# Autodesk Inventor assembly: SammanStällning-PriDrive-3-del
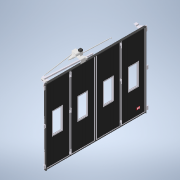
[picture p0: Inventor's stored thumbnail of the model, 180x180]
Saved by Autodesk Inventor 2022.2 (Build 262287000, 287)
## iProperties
Created: 2022-02
Part Number: SammanStällning-PriDrive-3-del
Document SubType Name: Assembly
Designer: cl
Author: cl
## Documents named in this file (22)
- G:\AutoCad\Carl Lund\3D-modeller systemlösningar\3D-modell-systemlösning-2022\SammanStällning-PriDrive-3-del.iam
- G:\AutoCad\Carl Lund\3D-modeller systemlösningar\3D-modell-systemlösning-2022\Parts\BladKomplett2022.iam
- G:\AutoCad\Carl Lund\3D-modeller systemlösningar\3D-modell-systemlösning-2022\Parts\MellanGångjärnH.ipt
- G:\AutoCad\Carl Lund\3D-modeller systemlösningar\3D-modell-systemlösning-2022\Parts\MellanGångjärnV.ipt
- G:\AutoCad\Carl Lund\3D-modeller systemlösningar\3D-modell-systemlösning-2022\Parts\Karmstyrning.ipt
- G:\AutoCad\Carl Lund\3D-modeller systemlösningar\3D-modell-systemlösning-2022\Parts\SidotätningUppe.ipt
- G:\AutoCad\Carl Lund\3D-modeller systemlösningar\3D-modell-systemlösning-2022\Parts\SidoTätning.ipt
- G:\AutoCad\Carl Lund\3D-modeller systemlösningar\3D-modell-systemlösning-2022\Parts\SläpList.ipt
- G:\AutoCad\Carl Lund\3D-modeller systemlösningar\3D-modell-systemlösning-2022\Parts\GummilistMellan.ipt
- G:\AutoCad\Carl Lund\3D-modeller systemlösningar\3D-modell-systemlösning-2022\Styrande.iam
- G:\AutoCad\Carl Lund\3D-modeller systemlösningar\3D-modell-systemlösning-2022\Parts\PriDrive\Karmgångjärn-PriDrive.ipt
- G:\AutoCad\Carl Lund\3D-modeller systemlösningar\3D-modell-systemlösning-2022\Parts\PriDrive\VinkeljärnStyrskena2.ipt
- G:\AutoCad\Carl Lund\3D-modeller systemlösningar\3D-modell-systemlösning-2022\Parts\PriDrive\VinkeljärnStyrskena.ipt
- G:\AutoCad\Carl Lund\3D-modeller systemlösningar\3D-modell-systemlösning-2022\Parts\StyrrulleH.ipt
- G:\AutoCad\Carl Lund\3D-modeller systemlösningar\3D-modell-systemlösning-2022\Parts\MotorKåpa.ipt
- G:\AutoCad\Carl Lund\3D-modeller systemlösningar\3D-modell-systemlösning-2022\Parts\Motor.ipt
- G:\AutoCad\Carl Lund\3D-modeller systemlösningar\3D-modell-systemlösning-2022\Parts\Växellåda.ipt
- G:\AutoCad\Carl Lund\3D-modeller systemlösningar\3D-modell-systemlösning-2022\Parts\MotorPlatta-3del.ipt
- G:\AutoCad\Carl Lund\3D-modeller systemlösningar\3D-modell-systemlösning-2022\Parts\Länkarm2-3Del.ipt
- G:\AutoCad\Carl Lund\3D-modeller systemlösningar\3D-modell-systemlösning-2022\Parts\Länkarm-3Del.ipt
- G:\AutoCad\Carl Lund\3D-modeller systemlösningar\3D-modell-systemlösning-2022\Parts\Styrskena-PD.ipt
- G:\AutoCad\Carl Lund\3D-modeller systemlösningar\3D-modell-systemlösning-2022\Parts\Logga.ipt
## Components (43 placed, 20 different names)
1. Logga:1 — Mate:200, Mate:201, Mate:202
2. BladKomplett2022:1 [sub-assembly] — Mate:1, Mate:2, Flush:1, Flush:2, Flush:3, Flush:8, Flush:28, Flush:29, Mate:28, Flush:30, Mate:42, Mate:39, Mate:43, Flush:99, Flush:100, Flush:101, Flush:102, Flush:103, Flush:104, Flush:112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
3. BladKomplett2022:2 [sub-assembly] — Flush:2, Flush:3, Flush:8, Flush:106, Mate:52, Flush:107, Flush:118, Flush:121, Mate:65, Flush:148, Flush:149, Mate:185, Flush:182, Flush:183, Flush:197
4. BladKomplett2022:3 [sub-assembly] — Flush:30, Flush:101, Flush:102, Mate:53, Flush:114, Flush:115, Flush:180, Mate:198
5. BladKomplett2022:4 [sub-assembly] — Flush:32, Flush:100, Flush:103, Mate:54, Flush:122, Flush:123, Flush:128, Mate:64, Flush:146, Flush:147
6. BladKomplett2022:5 [sub-assembly] — Flush:31, Flush:99, Flush:104, Flush:129, Mate:55, Flush:130, Mate:63, Flush:144, Flush:145, Flush:189
7. BladKomplett2022:6 [sub-assembly] — Mate:28, Flush:28, Flush:29, Flush:31, Flush:32, Mate:38, Flush:131, Flush:134, Flush:137, Mate:56, Flush:138, Flush:139, Mate:58, Mate:59, Mate:62, Flush:142, Flush:143, Flush:152, Mate:69, Mate:70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
8. Karmstyrning:2 — Mate:38, Mate:56, Flush:138, Flush:141
9. Karmstyrning:3 — Mate:39, Mate:43, Flush:140
10. Karmstyrning:4 — Mate:42, Mate:60, Mate:61, Flush:141
11. Karmstyrning:1 — Flush:139, Mate:58, Mate:59, Flush:140
12. MellanGångjärnV:3 — Flush:110, Flush:111, Flush:113
13. MellanGångjärnV:2 — Flush:108, Flush:109, Flush:110, Flush:111, Flush:112
14. MellanGångjärnV:1 — Flush:106, Mate:52, Flush:107, Flush:108, Flush:109
15. MellanGångjärnH:2 — Flush:116, Flush:117, Flush:118, Flush:119, Flush:120
16. MellanGångjärnH:3 — Flush:119, Flush:120, Flush:121
17. MellanGångjärnH:1 — Mate:53, Flush:114, Flush:115, Flush:116, Flush:117
18. MellanGångjärnV:6 — Flush:124, Flush:125, Flush:126, Flush:127, Flush:128
19. MellanGångjärnV:5 — Flush:126, Flush:127, Flush:129
20. MellanGångjärnV:4 — Mate:54, Flush:122, Flush:123, Flush:124, Flush:125
21. MellanGångjärnH:5 — Flush:132, Flush:133, Flush:134
22. MellanGångjärnH:6 — Flush:135, Flush:136, Flush:137
23. MellanGångjärnH:4 — Mate:55, Flush:130, Flush:131, Flush:132, Flush:133, Flush:135, Flush:136
24. GummilistMellan:2 — Mate:63, Flush:144, Flush:145
25. GummilistMellan:3 — Mate:64, Flush:146, Flush:147
26. GummilistMellan:4 — Mate:65, Flush:148, Flush:149
27. GummilistMellan:5 — Mate:66, Flush:150, Flush:151
28. SidotätningUppe:1 — Mate:67, Mate:68, Flush:152, Mate:71, Mate:74
29. SidoTätning:1 — Mate:69, Mate:70, Mate:71, Mate:76
30. SidoTätning:2 — Mate:72, Mate:73, Mate:74
31. SläpList:1 — Mate:75, Flush:153, Mate:76
32. GummilistMellan:1 — Mate:62, Flush:142, Flush:143
33. Karmgångjärn-PriDrive:1 — Mate:177, Flush:176, Mate:178, Flush:179, Mate:188, Tangent:3, Tangent:4
34. VinkeljärnStyrskena2:1 — Flush:179, Flush:180, Mate:181, Mate:183, Flush:187
35. VinkeljärnStyrskena:2 — Mate:187, Flush:187, Mate:199
36. StyrrulleH:1 — Mate:185, Flush:182, Flush:183, Tangent:2
37. Styrskena-PD:1 — Mate:181, Mate:183, Tangent:2, Mate:187, Mate:198
38. Länkarm-3Del:1 — Flush:190, Tangent:3, Flush:191, Mate:197
39. Länkarm2-3Del:1 — Flush:191, Mate:196, Tangent:4
40. MotorKåpa:1 — Mate:195, Flush:195, Flush:196
41. Motor:1 — Mate:193, Flush:194, Mate:194, Mate:195, Flush:195, Flush:196
42. Växellåda:1 — Mate:192, Flush:192, Flush:193, Flush:194, Mate:194
43. MotorPlatta-3del:1 — Mate:188, Flush:189, Flush:190, Mate:192, Flush:192, Flush:193, Mate:193, Flush:197, Mate:196, Mate:197, Mate:199
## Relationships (130: Flush 78, Mate 49, Tangent 3)
- Mate:1: BladKomplett2022:1
- Mate:2: BladKomplett2022:1
- Flush:1: BladKomplett2022:1
- Flush:2: BladKomplett2022:1 ↔ BladKomplett2022:2
- Flush:3: BladKomplett2022:1 ↔ BladKomplett2022:2
- Flush:8: BladKomplett2022:1 ↔ BladKomplett2022:2
- Mate:28: BladKomplett2022:1 ↔ BladKomplett2022:6
- Flush:28: BladKomplett2022:1 ↔ BladKomplett2022:6
- Flush:29: BladKomplett2022:1 ↔ BladKomplett2022:6
- Flush:30: BladKomplett2022:1 ↔ BladKomplett2022:3
- Flush:31: BladKomplett2022:5 ↔ BladKomplett2022:6
- Flush:32: BladKomplett2022:4 ↔ BladKomplett2022:6
- Mate:38: BladKomplett2022:6 ↔ Karmstyrning:2
- Mate:39: BladKomplett2022:1 ↔ Karmstyrning:3
- Mate:42: BladKomplett2022:1 ↔ Karmstyrning:4
- Mate:43: BladKomplett2022:1 ↔ Karmstyrning:3
- Flush:99: BladKomplett2022:1 ↔ BladKomplett2022:5
- Flush:100: BladKomplett2022:1 ↔ BladKomplett2022:4
- Flush:101: BladKomplett2022:1 ↔ BladKomplett2022:3
- Flush:102: BladKomplett2022:1 ↔ BladKomplett2022:3
- Flush:103: BladKomplett2022:1 ↔ BladKomplett2022:4
- Flush:104: BladKomplett2022:1 ↔ BladKomplett2022:5
- Flush:106: BladKomplett2022:2 ↔ MellanGångjärnV:1
- Mate:52: BladKomplett2022:2 ↔ MellanGångjärnV:1
- Flush:107: BladKomplett2022:2 ↔ MellanGångjärnV:1
- Flush:108: MellanGångjärnV:2 ↔ MellanGångjärnV:1
- Flush:109: MellanGångjärnV:2 ↔ MellanGångjärnV:1
- Flush:110: MellanGångjärnV:3 ↔ MellanGångjärnV:2
- Flush:111: MellanGångjärnV:3 ↔ MellanGångjärnV:2
- Flush:112: BladKomplett2022:1 ↔ MellanGångjärnV:2
- Flush:113: BladKomplett2022:1 ↔ MellanGångjärnV:3
- Mate:53: BladKomplett2022:3 ↔ MellanGångjärnH:1
- Flush:114: BladKomplett2022:3 ↔ MellanGångjärnH:1
- Flush:115: BladKomplett2022:3 ↔ MellanGångjärnH:1
- Flush:116: MellanGångjärnH:2 ↔ MellanGångjärnH:1
- Flush:117: MellanGångjärnH:2 ↔ MellanGångjärnH:1
- Flush:118: BladKomplett2022:2 ↔ MellanGångjärnH:2
- Flush:119: MellanGångjärnH:2 ↔ MellanGångjärnH:3
- Flush:120: MellanGångjärnH:2 ↔ MellanGångjärnH:3
- Flush:121: BladKomplett2022:2 ↔ MellanGångjärnH:3
- Mate:54: BladKomplett2022:4 ↔ MellanGångjärnV:4
- Flush:122: BladKomplett2022:4 ↔ MellanGångjärnV:4
- Flush:123: BladKomplett2022:4 ↔ MellanGångjärnV:4
- Flush:124: MellanGångjärnV:6 ↔ MellanGångjärnV:4
- Flush:125: MellanGångjärnV:6 ↔ MellanGångjärnV:4
- Flush:126: MellanGångjärnV:6 ↔ MellanGångjärnV:5
- Flush:127: MellanGångjärnV:6 ↔ MellanGångjärnV:5
- Flush:128: BladKomplett2022:4 ↔ MellanGångjärnV:6
- Flush:129: BladKomplett2022:5 ↔ MellanGångjärnV:5
- Mate:55: BladKomplett2022:5 ↔ MellanGångjärnH:4
- Flush:130: BladKomplett2022:5 ↔ MellanGångjärnH:4
- Flush:131: BladKomplett2022:6 ↔ MellanGångjärnH:4
- Flush:132: MellanGångjärnH:5 ↔ MellanGångjärnH:4
- Flush:133: MellanGångjärnH:5 ↔ MellanGångjärnH:4
- Flush:134: BladKomplett2022:6 ↔ MellanGångjärnH:5
- Flush:135: MellanGångjärnH:6 ↔ MellanGångjärnH:4
- Flush:136: MellanGångjärnH:6 ↔ MellanGångjärnH:4
- Flush:137: BladKomplett2022:6 ↔ MellanGångjärnH:6
- Mate:56: BladKomplett2022:6 ↔ Karmstyrning:2
- Flush:138: BladKomplett2022:6 ↔ Karmstyrning:2
- Flush:139: BladKomplett2022:6 ↔ Karmstyrning:1
- Mate:58: BladKomplett2022:6 ↔ Karmstyrning:1
- Mate:59: BladKomplett2022:6 ↔ Karmstyrning:1
- Flush:140: Karmstyrning:3 ↔ Karmstyrning:1
- Mate:60: BladKomplett2022:1 ↔ Karmstyrning:4
- Mate:61: BladKomplett2022:1 ↔ Karmstyrning:4
- Flush:141: Karmstyrning:2 ↔ Karmstyrning:4
- Mate:62: BladKomplett2022:6 ↔ GummilistMellan:1
- Flush:142: BladKomplett2022:6 ↔ GummilistMellan:1
- Flush:143: BladKomplett2022:6 ↔ GummilistMellan:1
- Mate:63: BladKomplett2022:5 ↔ GummilistMellan:2
- Flush:144: BladKomplett2022:5 ↔ GummilistMellan:2
- Flush:145: BladKomplett2022:5 ↔ GummilistMellan:2
- Mate:64: BladKomplett2022:4 ↔ GummilistMellan:3
- Flush:146: BladKomplett2022:4 ↔ GummilistMellan:3
- Flush:147: BladKomplett2022:4 ↔ GummilistMellan:3
- Mate:65: BladKomplett2022:2 ↔ GummilistMellan:4
- Flush:148: BladKomplett2022:2 ↔ GummilistMellan:4
- Flush:149: BladKomplett2022:2 ↔ GummilistMellan:4
- Mate:66: BladKomplett2022:1 ↔ GummilistMellan:5
- Flush:150: BladKomplett2022:1 ↔ GummilistMellan:5
- Flush:151: BladKomplett2022:1 ↔ GummilistMellan:5
- Mate:67: BladKomplett2022:1 ↔ SidotätningUppe:1
- Mate:68: BladKomplett2022:1 ↔ SidotätningUppe:1
- Flush:152: BladKomplett2022:6 ↔ SidotätningUppe:1
- Mate:69: BladKomplett2022:6 ↔ SidoTätning:1
- Mate:70: BladKomplett2022:6 ↔ SidoTätning:1
- Mate:71: SidotätningUppe:1 ↔ SidoTätning:1
- Mate:72: BladKomplett2022:1 ↔ SidoTätning:2
- Mate:73: BladKomplett2022:1 ↔ SidoTätning:2
- Mate:74: SidotätningUppe:1 ↔ SidoTätning:2
- Mate:75: BladKomplett2022:1 ↔ SläpList:1
- Flush:153: BladKomplett2022:1 ↔ SläpList:1
- Mate:76: SidoTätning:1 ↔ SläpList:1
- Mate:177: BladKomplett2022:1 ↔ Karmgångjärn-PriDrive:1
- Flush:176: BladKomplett2022:1 ↔ Karmgångjärn-PriDrive:1
- Mate:178: BladKomplett2022:1 ↔ Karmgångjärn-PriDrive:1
- Flush:179: Karmgångjärn-PriDrive:1 ↔ VinkeljärnStyrskena2:1
- Flush:180: BladKomplett2022:3 ↔ VinkeljärnStyrskena2:1
- Mate:181: VinkeljärnStyrskena2:1 ↔ Styrskena-PD:1
- Mate:183: VinkeljärnStyrskena2:1 ↔ Styrskena-PD:1
- Mate:185: BladKomplett2022:2 ↔ StyrrulleH:1
- Flush:182: BladKomplett2022:2 ↔ StyrrulleH:1
- Flush:183: BladKomplett2022:2 ↔ StyrrulleH:1
- Tangent:2: StyrrulleH:1 ↔ Styrskena-PD:1
- Mate:187: VinkeljärnStyrskena:2 ↔ Styrskena-PD:1
- Flush:187: VinkeljärnStyrskena2:1 ↔ VinkeljärnStyrskena:2
- Mate:188: Karmgångjärn-PriDrive:1 ↔ MotorPlatta-3del:1
- Flush:189: BladKomplett2022:5 ↔ MotorPlatta-3del:1
- Flush:190: Länkarm-3Del:1 ↔ MotorPlatta-3del:1
- Tangent:3: Karmgångjärn-PriDrive:1 ↔ Länkarm-3Del:1
- Flush:191: Länkarm-3Del:1 ↔ Länkarm2-3Del:1
- Mate:192: Växellåda:1 ↔ MotorPlatta-3del:1
- Flush:192: Växellåda:1 ↔ MotorPlatta-3del:1
- Flush:193: Växellåda:1 ↔ MotorPlatta-3del:1
- Mate:193: Motor:1 ↔ MotorPlatta-3del:1
- Flush:194: Motor:1 ↔ Växellåda:1
- Mate:194: Motor:1 ↔ Växellåda:1
- Mate:195: MotorKåpa:1 ↔ Motor:1
- Flush:195: MotorKåpa:1 ↔ Motor:1
- Flush:196: MotorKåpa:1 ↔ Motor:1
- Flush:197: BladKomplett2022:2 ↔ MotorPlatta-3del:1
- Mate:196: Länkarm2-3Del:1 ↔ MotorPlatta-3del:1
- Tangent:4: Karmgångjärn-PriDrive:1 ↔ Länkarm2-3Del:1
- Mate:197: Länkarm-3Del:1 ↔ MotorPlatta-3del:1
- Mate:198: BladKomplett2022:3 ↔ Styrskena-PD:1
- Mate:199: VinkeljärnStyrskena:2 ↔ MotorPlatta-3del:1
- Mate:200: Logga:1 ↔ BladKomplett2022:6
- Mate:201: Logga:1 ↔ BladKomplett2022:6
- Mate:202: Logga:1 ↔ BladKomplett2022:6
## Named parameters: Blad2 = 1012.5 mm, Blad3 = 0, Blad4 = 0, Blad5 = 1012.5 mm, MGJ12Djup = 0, MGJ12Bredd = 0, MGJ56Djup = 0, MGJ56Bredd = 0, MGJ23Djup = 48 mm, MGJ45Djup = 48 mm, GarageRegel5 = 0, GarageRegel6 = 0, BladBredd = 987.5 mm, Fönsterhöjd = 862 mm, Blad2_1 = 1012.5 mm, Blad3_1 = 0, Blad4_1 = 0, Blad5_1 = 1012.5 mm, Blad6 = 2025 mm, MGJ12Djup_1 = 0, MGJ12Bredd_1 = 0, MGJ2Djup = 0, MGJ2Bredd = 5012.5 mm, MGJ56Djup_1 = 0, MGJ56Bredd_1 = 0, MGJ23Djup_1 = 48 mm, MGJ45Djup_1 = 48 mm, GarageRegel5_1 = 0, GarageRegel6_1 = 0, Styrrulle2Djup = 0, FönsterhöjdStyrning = 862 mm, FönsterKarm = 54 mm, AndraGlasraden = 0, BrösthöjdStyrning2 = 0.0001 mm, InfälldGångDörr = 0, Infälldstyr = 1030.33333 mm, EnDelGångDörr = 0, VinkelJärnStyrSkena = 1456.25 mm
